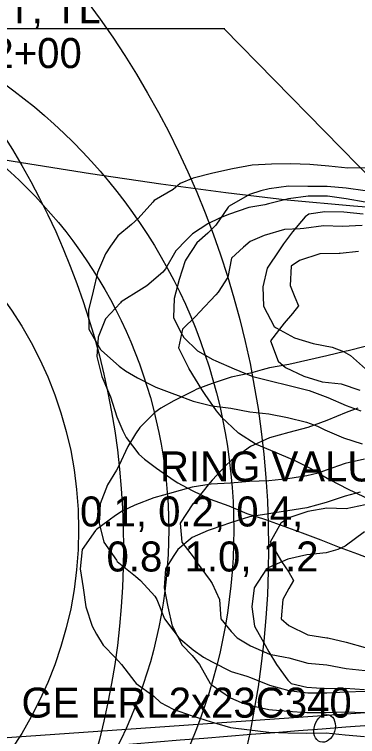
# Model space of a CAD drawing. Extents: x 1638506 to 1658005, y 834807 to 846788.
# Drawn here: x 1642259.2 to 1642396.4, y 842159.5 to 842448.1 of the extents above; entities that cross this region are included whole.
import ezdxf

# ---------------------------------------------------------------- set-up
doc = ezdxf.new("R2010")
doc.units = 0
for name, color, linetype in [('Default', 7, 'Continuous'), ('Old_Level_1', 7, 'Continuous'), ('Old_Level_2', 7, 'Continuous'), ('Scratch_Level_0', 7, 'Continuous')]:
    doc.layers.add(name, color=color, linetype=linetype)

msp = doc.modelspace()

# ---------------------------------------------------------------- linework, layer by layer
at = {"layer": 'Default'}
for p, q in [((1642151.91, 842442.51), (1642343.37, 842442.51)), ((1642342.93, 842442.48), (1642478.26, 842304.41))]:
    msp.add_line(p, q, dxfattribs=at)
msp.add_arc((1643863.61, 823017.34), 19202.35, 94.226402, 95.13232, dxfattribs=at)
msp.add_ellipse((1642383.2, 842162.72), major_axis=(1.72, 5.4), ratio=0.730797, dxfattribs=at)
at = {"layer": 'Old_Level_1'}
for points in [[(1642400.19, 842386.86), (1642392.49, 842386.69), (1642384.89, 842387.5), (1642377.26, 842388.13), (1642369.61, 842388.46), (1642361.91, 842388.21), (1642354.2, 842387.91), (1642346.39, 842386.36), (1642346.33, 842386.35), (1642338.57, 842384.7), (1642330.71, 842382.67), (1642325.46, 842380.49), (1642322.64, 842378.18), (1642315.08, 842373.72), (1642314.52, 842373.13), (1642308.63, 842366.61), (1642306.05, 842364.15), (1642300.59, 842359.63), (1642297.61, 842355.45), (1642295.59, 842352.39), (1642292.43, 842344.99), (1642290.7, 842337.46), (1642288.81, 842329.95), (1642288.88, 842322.26), (1642293.6, 842314.17)], [(1642399.38, 842377.68), (1642391.79, 842378.64), (1642384.17, 842379.3), (1642376.5, 842379.41), (1642368.82, 842379.44), (1642361.05, 842378.4), (1642357.65, 842377.68), (1642353.18, 842376.15), (1642345.09, 842371.46), (1642344.59, 842371.14), (1642339.74, 842363.89), (1642336.46, 842360.64), (1642332.14, 842356.87), (1642327.87, 842350.27), (1642327.47, 842349.6), (1642325.1, 842342.13), (1642323, 842334.63), (1642322.81, 842326.97)], [(1642398.57, 842368.33), (1642390.96, 842369.14), (1642383.28, 842369.18), (1642376.87, 842368.32), (1642375.43, 842367.16), (1642370.34, 842361.21), (1642366.81, 842356.44), (1642365.23, 842353.98), (1642360.28, 842346.73), (1642358.56, 842339.2), (1642358.81, 842331.5), (1642363.05, 842323.45)], [(1642322.81, 842326.97), (1642325.38, 842321.8), (1642326.99, 842318.93), (1642332.35, 842313.65), (1642338.49, 842310.24), (1642339.68, 842309.72), (1642347.08, 842306.46), (1642354.49, 842303.35), (1642362, 842301.47), (1642368.44, 842299.94), (1642369.52, 842299.66), (1642377.04, 842297.82), (1642384.47, 842294.99), (1642391.88, 842291.85), (1642397.64, 842289.71)], [(1642363.05, 842323.45), (1642363.88, 842322.91), (1642371.21, 842318.92), (1642378.68, 842316.53), (1642386.23, 842315.12), (1642390.72, 842313.35), (1642393.62, 842311.77), (1642400.74, 842305.35)], [(1642293.6, 842314.17), (1642293.97, 842313.83), (1642301.09, 842307.51), (1642303.58, 842305.62), (1642308.36, 842302.8), (1642315.72, 842299.11), (1642323.16, 842296.36), (1642323.58, 842296.19), (1642330.59, 842293.6), (1642338.11, 842291.7), (1642345.7, 842290.68), (1642353.25, 842289.29), (1642360.86, 842288.41), (1642368.41, 842286.96), (1642375.92, 842285.08), (1642380.31, 842283.54), (1642383.35, 842282.13), (1642390.74, 842278.87), (1642398.21, 842276.45)], [(1642399.11, 842270.33), (1642391.46, 842268.57), (1642383.81, 842265.97), (1642380.66, 842264.82), (1642376.16, 842263.68), (1642368.51, 842262.46), (1642360.86, 842261.67), (1642353.21, 842261.46), (1642345.56, 842260.73), (1642337.91, 842260.38), (1642330.26, 842259.14), (1642323.05, 842257.17), (1642322.61, 842257.04), (1642314.96, 842254.95), (1642307.31, 842251.91), (1642302.3, 842249.52), (1642299.66, 842247.85), (1642292.01, 842242.18), (1642291.61, 842241.87), (1642286.21, 842234.22), (1642285.47, 842226.57), (1642286.7, 842218.92), (1642287.76, 842211.27), (1642290.27, 842203.62), (1642292.01, 842200.4), (1642294.62, 842195.97), (1642299.66, 842190.99), (1642302.02, 842188.32), (1642307.31, 842181.31), (1642307.82, 842180.67), (1642314.96, 842175.58), (1642317.57, 842173.02), (1642322.61, 842170.4), (1642330.26, 842167.69), (1642337.86, 842165.37), (1642337.91, 842165.36), (1642345.56, 842163.13), (1642353.21, 842162.16), (1642360.86, 842161.24), (1642368.51, 842160.91), (1642376.16, 842160.86), (1642383.81, 842161.01), (1642391.46, 842160.17), (1642399.11, 842159.52)], [(1642397.4, 842257.17), (1642391.46, 842255.54), (1642383.81, 842253.06), (1642376.16, 842250.88), (1642368.51, 842249.71), (1642367.41, 842249.52), (1642360.86, 842248.56), (1642353.21, 842247.34), (1642345.56, 842244.89), (1642337.91, 842242.29), (1642336.68, 842241.87), (1642330.26, 842239.01), (1642324.46, 842234.22), (1642322.61, 842231.5), (1642319.6, 842226.57), (1642319.12, 842218.92), (1642320.56, 842211.27), (1642322.27, 842203.62), (1642322.61, 842202.92), (1642326.29, 842195.97), (1642330.26, 842191.85), (1642333.25, 842188.32), (1642337.45, 842180.67), (1642337.91, 842180.31), (1642345.56, 842174.94), (1642349.89, 842173.02), (1642353.21, 842172.01), (1642360.86, 842170.29), (1642368.51, 842169.65), (1642376.16, 842169.1), (1642383.81, 842169.09), (1642391.46, 842169.38), (1642399.11, 842169.08)], [(1642399.11, 842241.32), (1642391.46, 842235.55), (1642388.44, 842234.22), (1642383.81, 842232.85), (1642376.16, 842232.1), (1642368.51, 842230.38), (1642360.86, 842227.04), (1642359.99, 842226.57), (1642355.07, 842218.92), (1642354.14, 842211.27), (1642355.2, 842203.62), (1642359.5, 842195.97), (1642360.86, 842193.38), (1642363.96, 842188.32), (1642368.51, 842181.95), (1642369.85, 842180.67), (1642376.16, 842179.26), (1642383.81, 842178.63), (1642391.46, 842178.77), (1642399.11, 842178.34)]]:
    msp.add_lwpolyline(points, dxfattribs=at)
for radius in [365, 307]:
    msp.add_circle((1641995.81, 842234.97), radius, dxfattribs=at)
at = {"layer": 'Old_Level_2'}
msp.add_line((1642519.11, 842177.39), (1642217.73, 842156.22), dxfattribs=at)
msp.add_lwpolyline([(1642025.39, 842444.99), (1642047.66, 842437.99), (1642090.85, 842425.3), (1642111.35, 842420.03), (1642135.93, 842413.98), (1642180.4, 842403.97), (1642212.86, 842397.26), (1642258.65, 842389.41), (1642289.59, 842384.48), (1642317.7, 842380.48), (1642343.73, 842376.94), (1642368.27, 842374.07), (1642394.7, 842371.65), (1642420.5, 842369.62)], dxfattribs=at)
at = {"layer": 'Scratch_Level_0'}
for points in [[(1642399.42, 842373.05), (1642391.89, 842374.44), (1642384.3, 842375.44), (1642376.59, 842375.48), (1642368.73, 842374.4), (1642360.75, 842372.36), (1642359.28, 842372.03), (1642352.85, 842370.96), (1642344.76, 842368.16), (1642341.13, 842366.7), (1642336.55, 842364.38), (1642330.37, 842360.4), (1642327.99, 842358.02), (1642323.66, 842353.57), (1642319.64, 842346.39), (1642318.57, 842345.07), (1642312.15, 842339.66), (1642309.96, 842338.27), (1642301.88, 842333.29), (1642301.54, 842332.91), (1642295.6, 842326.41), (1642292.72, 842319.07), (1642292.1, 842311.43), (1642294.1, 842303.45)], [(1642398.2, 842363.79), (1642390.42, 842363.35), (1642382.75, 842363.68), (1642374.9, 842362.62), (1642373.4, 842362.45), (1642367.12, 842362.17), (1642359.09, 842359.78), (1642353.4, 842357.37), (1642350.76, 842355.16), (1642345.95, 842350.64), (1642344.49, 842343.11), (1642340.68, 842337.17), (1642339.76, 842336.02), (1642333.23, 842329.16), (1642331.69, 842327.54), (1642326.44, 842322.34), (1642324.84, 842314.84), (1642328.87, 842306.59)], [(1642396.82, 842353.31), (1642389.37, 842352.63), (1642389.01, 842352.61), (1642381.27, 842352.41), (1642373.2, 842349.75), (1642369.86, 842347.48), (1642369.5, 842339.82), (1642371.27, 842335.12), (1642372.8, 842331.67), (1642370.41, 842328.57), (1642367.01, 842324.71), (1642361.53, 842317.72), (1642364.7, 842309.58)], [(1642399.44, 842315.38), (1642392.59, 842313.65), (1642391.79, 842313.46), (1642384.14, 842311.62), (1642376.49, 842309.92), (1642368.84, 842308.23), (1642361.19, 842306.81), (1642358.22, 842306), (1642353.54, 842304.74), (1642345.89, 842303.11), (1642338.24, 842300.64), (1642332.17, 842298.35), (1642330.59, 842297.59), (1642322.94, 842293.69), (1642317.71, 842290.7), (1642315.29, 842288.95), (1642309.35, 842283.05), (1642307.64, 842280.54), (1642304.57, 842275.4), (1642300.97, 842267.75), (1642299.99, 842265.98), (1642296.46, 842260.1), (1642293.44, 842252.45), (1642293.05, 842244.8), (1642294.95, 842237.15), (1642299.99, 842229.93), (1642300.28, 842229.5), (1642307.64, 842223.52), (1642309.63, 842221.85), (1642315.29, 842215.65), (1642316.17, 842214.2), (1642319.22, 842206.55), (1642322.94, 842201.58), (1642324.99, 842198.9), (1642330.59, 842194.16), (1642334.83, 842191.25), (1642338.24, 842189.34), (1642345.89, 842185.5), (1642352.12, 842183.6), (1642353.54, 842183.08), (1642361.19, 842180.01), (1642368.84, 842177.92), (1642376.49, 842176.95), (1642384.14, 842176.95), (1642391.79, 842177.35), (1642399.44, 842177.6)], [(1642364.7, 842309.58), (1642367.57, 842307.04), (1642374.84, 842303.59), (1642382.24, 842301.24), (1642389.85, 842300.46), (1642397.24, 842297.97)], [(1642328.87, 842306.59), (1642328.92, 842306.51), (1642333.99, 842298.2), (1642335.28, 842296.19), (1642339.87, 842289.71), (1642341.83, 842287.32), (1642348.69, 842280.85), (1642348.72, 842280.83), (1642355.81, 842276.36), (1642363.13, 842273.31), (1642370.41, 842270.25), (1642370.44, 842270.24), (1642377.67, 842266.57), (1642384.84, 842262.37), (1642389.32, 842260.04), (1642392.06, 842258.65), (1642399.32, 842255.16)], [(1642294.1, 842303.45), (1642296.83, 842297.17), (1642297.57, 842295.28), (1642300.14, 842287.23), (1642302.51, 842281.74), (1642303.88, 842279.02), (1642308.99, 842272.39), (1642311.17, 842270.34), (1642315.96, 842266.7), (1642323.03, 842261.83), (1642324.5, 842260.87), (1642330.22, 842257.81), (1642337.48, 842254.36), (1642344.85, 842251.74), (1642349.34, 842249.88), (1642352.17, 842248.69), (1642359.57, 842246.29), (1642366.93, 842243.61), (1642374.29, 842240.93), (1642381.64, 842238.1), (1642382.41, 842237.81), (1642388.97, 842235.2), (1642396.33, 842232.45), (1642403.67, 842229.66)], [(1642396.53, 842290.7), (1642391.79, 842288.98), (1642384.14, 842285.75), (1642376.49, 842283.06), (1642376.45, 842283.05), (1642368.84, 842280.97), (1642361.19, 842278.9), (1642353.57, 842275.4), (1642353.54, 842275.38), (1642345.89, 842269.87), (1642343.63, 842267.75), (1642338.24, 842261.93), (1642336.7, 842260.1), (1642330.59, 842252.53), (1642330.53, 842252.45), (1642325.45, 842244.8), (1642326.06, 842237.15), (1642330.59, 842231.31), (1642331.9, 842229.5), (1642337.47, 842221.85), (1642338.24, 842220.59), (1642341.24, 842214.2), (1642341.71, 842206.55), (1642345.89, 842201.44), (1642348.21, 842198.9), (1642353.54, 842195.77), (1642361.19, 842192.35), (1642367.38, 842191.25), (1642368.84, 842190.89), (1642376.49, 842188.81), (1642384.14, 842188.14), (1642391.79, 842186.68), (1642399.44, 842185.94)], [(1642399.44, 842252.07), (1642391.79, 842250.56), (1642384.14, 842250.78), (1642376.49, 842249.42), (1642368.84, 842246.95), (1642365.66, 842244.8), (1642361.45, 842237.15), (1642365.97, 842229.5), (1642368.84, 842225.23), (1642370.8, 842221.85), (1642368.84, 842218.63), (1642366.46, 842214.2), (1642365.82, 842206.55), (1642368.84, 842203.87), (1642376.49, 842200.18), (1642384.14, 842198.97), (1642384.5, 842198.9), (1642391.79, 842197.26), (1642399.44, 842195.09)]]:
    msp.add_lwpolyline(points, dxfattribs=at)
for radius in [219, 193, 157]:
    msp.add_circle((1642127.87, 842242.15), radius, dxfattribs=at)

# ---------------------------------------------------------------- texts
at = {"layer": 'Default'}
for s, p in [('3" ELEC. DUCT, TL', (1642151.6, 842444.61)), ('-RPD- STA. 12+00', (1642151.91, 842426.69))]:
    msp.add_text(s, height=12, dxfattribs=at).set_placement(p)
at = {"layer": 'Scratch_Level_0'}
for s, p in [('RING VALUES', (1642317.41, 842261.45)), ('0.1, 0.2, 0.4,', (1642285.43, 842243.45)), ('0.8, 1.0, 1.2', (1642296.01, 842225.45)), ('GE ERL2x23C340', (1642262.03, 842167.03))]:
    msp.add_text(s, height=12, dxfattribs=at).set_placement(p)

doc.saveas('drawing.dxf')
